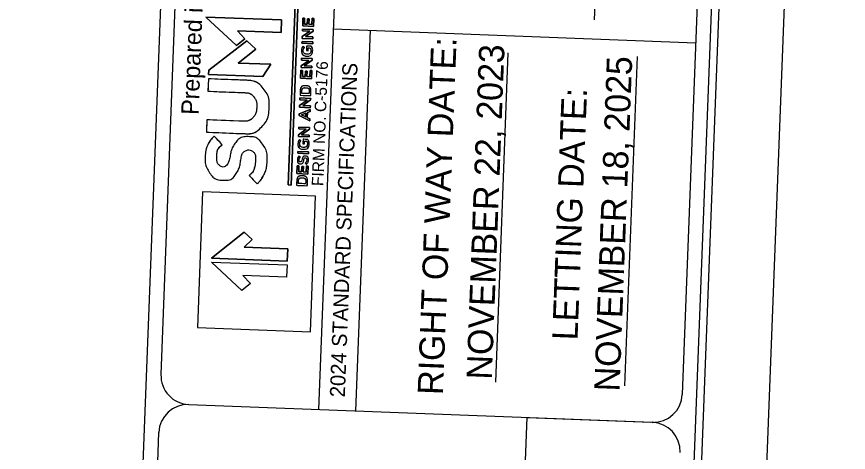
# Model space of a CAD drawing. Extents: x 2094564 to 2100382, y 679033 to 692366.
# Drawn here: x 2098948 to 2100382, y 686841 to 687593 of the extents above; entities that cross this region are included whole.
import ezdxf

# ---------------------------------------------------------------- set-up
doc = ezdxf.new("R2010")
doc.units = 0
for name, color, linetype in [('Old_Level_2', 7, 'Continuous'), ('Prop EOT', 7, 'Continuous'), ('Prop Horizontal Alignment Direction Label', 7, 'Continuous'), ('Prop Horizontal Alignment Tick Label', 7, 'Continuous'), ('Prop Horizontal Alignment Tick Large', 7, 'Continuous'), ('Scratch_Level_0', 7, 'Continuous')]:
    doc.layers.add(name, color=color, linetype=linetype)

msp = doc.modelspace()

# ---------------------------------------------------------------- linework, layer by layer
at = {"layer": 'Old_Level_2'}
for p, q in [((2099444.2, 687539.6), (2099441.8, 687541.8)), ((2099448.4, 687528.2), (2099448.3, 687528.2)), ((2099448.3, 687524.8), (2099448.3, 687524.8)), ((2099446.2, 687470.3), (2099446.2, 687470.3)), ((2099446.3, 687473.7), (2099446.3, 687473.7)), ((2099302.2, 687371.9), (2099288.5, 687386.7)), ((2099438, 687378.7), (2099435.6, 687380.8)), ((2099442.2, 687367.3), (2099442.2, 687367.3)), ((2099436.8, 687350.3), (2099434.4, 687352.2)), ((2099442.1, 687363.9), (2099442.1, 687363.9)), ((2099445.7, 687352.3), (2099445.6, 687352.3)), ((2099436.9, 687342.3), (2099436.8, 687342.3)), ((2099437, 687339), (2099437, 687339)), ((2099445.4, 687339.9), (2099447.7, 687337.8)), ((2099445.8, 687349), (2099445.9, 687349)), ((2099348.7, 687318.8), (2099362.4, 687304.1)), ((2099440.2, 687314.8), (2099440.3, 687314.8)), ((2099440.3, 687318.2), (2099440.3, 687318.2))]:
    msp.add_line(p, q, dxfattribs=at)
for points in [[(2099440.8, 687820.2), (2099420.9, 687302.2), (2099416, 687302.4), (2099435.9, 687820.4), (2099440.8, 687820.2)], [(2099435.9, 687820.4), (2099416, 687302.4), (2099420.9, 687302.2), (2099440.8, 687820.2), (2099435.9, 687820.4)], [(2099274.1, 687592.2), (2099404.4, 687587.2), (2099403.6, 687565.8), (2099328.4, 687568.7), (2099341.4, 687554.9), (2099326.6, 687543), (2099274.1, 687592.2)], [(2099326.6, 687543), (2099341.4, 687554.9), (2099328.4, 687568.7), (2099403.6, 687565.8), (2099404.4, 687587.2), (2099274.1, 687592.2), (2099326.6, 687543)], [(2099441, 687576.9), (2099441.5, 687590.6), (2099444.4, 687590.5), (2099444, 687580), (2099448.8, 687579.8), (2099449.2, 687589.1), (2099452.1, 687589), (2099451.8, 687579.7), (2099456.7, 687579.5), (2099457.2, 687590.2), (2099460.1, 687590), (2099459.5, 687576.2), (2099441, 687576.9)], [(2099459.5, 687576.2), (2099460.1, 687590), (2099457.2, 687590.2), (2099456.7, 687579.5), (2099451.8, 687579.7), (2099452.1, 687589), (2099449.2, 687589.1), (2099448.8, 687579.8), (2099444, 687580), (2099444.4, 687590.5), (2099441.5, 687590.6), (2099441, 687576.9), (2099459.5, 687576.2)], [(2099440.1, 687555.4), (2099440.3, 687558.4), (2099453.5, 687567.9), (2099440.6, 687568.4), (2099440.8, 687571.6), (2099459.3, 687570.9), (2099459.2, 687568.1), (2099445.6, 687558.4), (2099458.8, 687557.9), (2099458.7, 687554.7), (2099440.1, 687555.4)], [(2099458.7, 687554.7), (2099458.8, 687557.9), (2099445.6, 687558.4), (2099459.2, 687568.1), (2099459.3, 687570.9), (2099440.8, 687571.6), (2099440.6, 687568.4), (2099453.5, 687567.9), (2099440.3, 687558.4), (2099440.1, 687555.4), (2099458.7, 687554.7)], [(2099279, 687500.7), (2099344.5, 687551.3), (2099359.9, 687536.7), (2099329.6, 687512.8), (2099386, 687510.7), (2099372.1, 687489.6), (2099278.8, 687493.2), (2099279, 687500.7)], [(2099278.8, 687493.2), (2099372.1, 687489.6), (2099386, 687510.7), (2099329.6, 687512.8), (2099359.9, 687536.7), (2099344.5, 687551.3), (2099279, 687500.7), (2099278.8, 687493.2)], [(2099439.8, 687546.9), (2099439.9, 687550.2), (2099458.5, 687549.5), (2099458.4, 687546.2), (2099439.8, 687546.9)], [(2099458.4, 687546.2), (2099458.5, 687549.5), (2099439.9, 687550.2), (2099439.8, 687546.9), (2099458.4, 687546.2)], [(2099455.6, 687541.9), (2099447.8, 687542.2), (2099447.5, 687534.3), (2099450.4, 687534.2), (2099450.6, 687538.9), (2099454, 687538.8)], [(2099438.2, 687505.1), (2099438.3, 687508.1), (2099451.5, 687517.5), (2099438.7, 687518), (2099438.8, 687521.2), (2099457.4, 687520.5), (2099457.3, 687517.8), (2099443.7, 687508.1), (2099456.9, 687507.6), (2099456.8, 687504.4), (2099438.2, 687505.1)], [(2099456.8, 687504.4), (2099456.9, 687507.6), (2099443.7, 687508.1), (2099457.3, 687517.8), (2099457.4, 687520.5), (2099438.8, 687521.2), (2099438.7, 687518), (2099451.5, 687517.5), (2099438.3, 687508.1), (2099438.2, 687505.1), (2099456.8, 687504.4)], [(2099437.5, 687486.5), (2099438, 687500.3), (2099440.9, 687500.2), (2099440.5, 687489.7), (2099445.4, 687489.5), (2099445.7, 687498.8), (2099448.6, 687498.7), (2099448.3, 687489.4), (2099453.3, 687489.2), (2099453.7, 687499.8), (2099456.6, 687499.7), (2099456.1, 687485.8), (2099437.5, 687486.5)], [(2099456.1, 687485.8), (2099456.6, 687499.7), (2099453.7, 687499.8), (2099453.3, 687489.2), (2099448.3, 687489.4), (2099448.6, 687498.7), (2099445.7, 687498.8), (2099445.4, 687489.5), (2099440.5, 687489.7), (2099440.9, 687500.2), (2099438, 687500.3), (2099437.5, 687486.5), (2099456.1, 687485.8)], [(2099345.7, 687483), (2099278.5, 687485.5), (2099277.6, 687464.2), (2099339.2, 687461.8)], [(2099435.6, 687436.4), (2099435.7, 687439.4), (2099448.9, 687448.9), (2099436.1, 687449.4), (2099436.2, 687452.6), (2099454.8, 687451.9), (2099454.7, 687449.1), (2099441.1, 687439.4), (2099454.3, 687438.9), (2099454.2, 687435.7), (2099435.6, 687436.4)], [(2099454.2, 687435.7), (2099454.3, 687438.9), (2099441.1, 687439.4), (2099454.7, 687449.1), (2099454.8, 687451.9), (2099436.2, 687452.6), (2099436.1, 687449.4), (2099448.9, 687448.9), (2099435.7, 687439.4), (2099435.6, 687436.4), (2099454.2, 687435.7)], [(2099436.6, 687464.2), (2099436.4, 687457.3), (2099455, 687456.6), (2099455.2, 687463.5)], [(2099452.2, 687463.6), (2099452.1, 687460), (2099439.5, 687460.5), (2099439.6, 687464.1)], [(2099434.9, 687422.1), (2099435, 687425.1), (2099454, 687432.5), (2099453.9, 687429.1), (2099449.3, 687427.4), (2099449, 687418.6), (2099453.4, 687416.5), (2099453.3, 687413.2), (2099434.9, 687422.1)], [(2099453.3, 687413.2), (2099453.4, 687416.5), (2099449, 687418.6), (2099449.3, 687427.4), (2099453.9, 687429.1), (2099454, 687432.5), (2099435, 687425.1), (2099434.9, 687422.1), (2099453.3, 687413.2)], [(2099446.4, 687426.3), (2099438.8, 687423.4), (2099446.2, 687419.9), (2099446.4, 687426.3)], [(2099446.2, 687419.9), (2099438.8, 687423.4), (2099446.4, 687426.3), (2099446.2, 687419.9)], [(2099337.3, 687412.5), (2099275.7, 687414.8), (2099274.9, 687393.5), (2099342.2, 687390.9)], [(2099433.6, 687386.1), (2099433.8, 687389.1), (2099447, 687398.5), (2099434.1, 687399), (2099434.3, 687402.2), (2099452.8, 687401.5), (2099452.7, 687398.8), (2099439.1, 687389.1), (2099452.3, 687388.6), (2099452.2, 687385.4), (2099433.6, 687386.1)], [(2099452.2, 687385.4), (2099452.3, 687388.6), (2099439.1, 687389.1), (2099452.7, 687398.8), (2099452.8, 687401.5), (2099434.3, 687402.2), (2099434.1, 687399), (2099447, 687398.5), (2099433.8, 687389.1), (2099433.6, 687386.1), (2099452.2, 687385.4)], [(2099449.5, 687381), (2099441.7, 687381.3), (2099441.4, 687373.4), (2099444.2, 687373.3), (2099444.4, 687378), (2099447.9, 687377.9)], [(2099432.5, 687357.1), (2099432.7, 687360.4), (2099451.2, 687359.6), (2099451.1, 687356.4), (2099432.5, 687357.1)], [(2099451.1, 687356.4), (2099451.2, 687359.6), (2099432.7, 687360.4), (2099432.5, 687357.1), (2099451.1, 687356.4)], [(2099431.2, 687321.9), (2099431.7, 687335.7), (2099434.6, 687335.6), (2099434.2, 687325.1), (2099439.1, 687324.9), (2099439.4, 687334.2), (2099442.3, 687334.1), (2099442, 687324.8), (2099447, 687324.6), (2099447.4, 687335.2), (2099450.3, 687335.1), (2099449.8, 687321.2), (2099431.2, 687321.9)], [(2099449.8, 687321.2), (2099450.3, 687335.1), (2099447.4, 687335.2), (2099447, 687324.6), (2099442, 687324.8), (2099442.3, 687334.1), (2099439.4, 687334.2), (2099439.1, 687324.9), (2099434.2, 687325.1), (2099434.6, 687335.6), (2099431.7, 687335.7), (2099431.2, 687321.9), (2099449.8, 687321.2)], [(2099430.7, 687308.7), (2099430.4, 687301.8), (2099449, 687301.1), (2099449.3, 687308)], [(2099446.3, 687308.1), (2099446.1, 687304.4), (2099433.5, 687304.9), (2099433.6, 687308.6)], [(2099268.3, 687290.3), (2099259.3, 687056.5), (2099454.3, 687049), (2099463.3, 687282.8), (2099268.3, 687290.3)], [(2099268.3, 687290.3), (2099259.3, 687056.5), (2099454.3, 687049), (2099463.3, 687282.8), (2099268.3, 687290.3)], [(2099340, 687221), (2099353.9, 687208), (2099339.9, 687195.3), (2099415.1, 687192.4), (2099414.3, 687171), (2099283.9, 687176), (2099340, 687221)], [(2099283.6, 687169.4), (2099414, 687164.4), (2099413.2, 687143.1), (2099338, 687146), (2099350.9, 687132.2), (2099336.2, 687120.3), (2099283.6, 687169.4)], [(2099283.6, 687169.4), (2099414, 687164.4), (2099413.2, 687143.1), (2099338, 687146), (2099350.9, 687132.2), (2099336.2, 687120.3), (2099283.6, 687169.4)]]:
    msp.add_lwpolyline(points, dxfattribs=at)
msp.add_lwpolyline([(2099283.9, 687176), (2099414.3, 687171), (2099415.1, 687192.4), (2099339.9, 687195.3), (2099353.9, 687208), (2099340, 687221)], close=True, dxfattribs=at)
for points, degree in [([(2099448.3, 687524.8), (2099448.3, 687524.8), (2099448.3, 687524.8), (2099448.3, 687524.8), (2099443.1, 687525), (2099438.8, 687529.2), (2099439, 687534.7), (2099439.2, 687538), (2099440.1, 687539.9), (2099441.8, 687541.8), (2099441.8, 687541.8), (2099444.2, 687539.6), (2099444.2, 687539.6), (2099442.9, 687538.2), (2099442.1, 687536.9), (2099442, 687534.5), (2099441.9, 687531.1), (2099444.8, 687528.4), (2099448.3, 687528.2), (2099448.3, 687528.2), (2099448.4, 687528.2), (2099448.4, 687528.2), (2099452.2, 687528.1), (2099455.1, 687530.5), (2099455.3, 687534.3), (2099455.3, 687536), (2099454.8, 687537.6), (2099454, 687538.8), (2099454, 687538.8), (2099450.6, 687538.9), (2099450.6, 687538.9), (2099450.6, 687538.9), (2099450.4, 687534.2), (2099450.4, 687534.2), (2099450.4, 687534.2), (2099447.5, 687534.3), (2099447.5, 687534.3), (2099447.5, 687534.3), (2099447.8, 687542.2), (2099447.8, 687542.2), (2099447.8, 687542.2), (2099455.6, 687541.9), (2099455.6, 687541.9), (2099457.1, 687540), (2099458.4, 687537.3), (2099458.2, 687534.1), (2099458, 687528.3), (2099453.7, 687524.6), (2099448.3, 687524.8)], 3), ([(2099441.8, 687541.8), (2099440.1, 687539.9), (2099439.2, 687538), (2099439, 687534.7), (2099438.8, 687529.2), (2099443.1, 687525), (2099448.3, 687524.8)], 3), ([(2099448.3, 687528.2), (2099444.8, 687528.4), (2099441.9, 687531.1), (2099442, 687534.5), (2099442.1, 687536.9), (2099442.9, 687538.2), (2099444.2, 687539.6)], 3), ([(2099448.3, 687524.8), (2099453.7, 687524.6), (2099458, 687528.3), (2099458.2, 687534.1), (2099458.4, 687537.3), (2099457.1, 687540), (2099455.6, 687541.9)], 3), ([(2099454, 687538.8), (2099454.8, 687537.6), (2099455.3, 687536), (2099455.3, 687534.3), (2099455.1, 687530.5), (2099452.2, 687528.1), (2099448.4, 687528.2)], 3), ([(2099275.7, 687414.8), (2099275.7, 687414.8), (2099337.3, 687412.5), (2099337.3, 687412.5), (2099345.4, 687412.2), (2099351.4, 687414.4), (2099355.4, 687418.9), (2099359.4, 687423.5), (2099361.5, 687429.4), (2099361.8, 687436.5), (2099362, 687443.6), (2099360.4, 687449.4), (2099356.7, 687454.3), (2099353.1, 687459.2), (2099347.3, 687461.5), (2099339.2, 687461.8), (2099339.2, 687461.8), (2099277.6, 687464.2), (2099277.6, 687464.2), (2099277.6, 687464.2), (2099278.5, 687485.5), (2099278.5, 687485.5), (2099278.5, 687485.5), (2099345.7, 687483), (2099345.7, 687483), (2099356.6, 687482.5), (2099365.7, 687478.1), (2099373, 687469), (2099380.3, 687459.9), (2099383.6, 687448.9), (2099383.1, 687435.6), (2099382.6, 687422.3), (2099378.4, 687411.4), (2099370.5, 687403), (2099362.5, 687394.5), (2099353.1, 687390.5), (2099342.2, 687390.9), (2099342.2, 687390.9), (2099274.9, 687393.5), (2099274.9, 687393.5), (2099274.9, 687393.5), (2099275.7, 687414.8), (2099275.7, 687414.8)], 3), ([(2099342.2, 687390.9), (2099353.1, 687390.5), (2099362.5, 687394.5), (2099370.5, 687403), (2099378.4, 687411.4), (2099382.6, 687422.3), (2099383.1, 687435.6), (2099383.6, 687448.9), (2099380.3, 687459.9), (2099373, 687469), (2099365.7, 687478.1), (2099356.6, 687482.5), (2099345.7, 687483)], 3), ([(2099436.4, 687457.3), (2099436.4, 687457.3), (2099436.6, 687464.2), (2099436.6, 687464.2), (2099436.9, 687470.1), (2099441, 687473.9), (2099446.3, 687473.7), (2099446.3, 687473.7), (2099446.3, 687473.7), (2099446.3, 687473.7), (2099451.5, 687473.5), (2099455.4, 687469.4), (2099455.2, 687463.5), (2099455.2, 687463.5), (2099455, 687456.6), (2099455, 687456.6), (2099455, 687456.6), (2099436.4, 687457.3), (2099436.4, 687457.3)], 3), ([(2099446.3, 687473.7), (2099441, 687473.9), (2099436.9, 687470.1), (2099436.6, 687464.2)], 2), ([(2099439.5, 687460.5), (2099439.5, 687460.5), (2099452.1, 687460), (2099452.1, 687460), (2099452.1, 687460), (2099452.2, 687463.6), (2099452.2, 687463.6), (2099452.4, 687467.5), (2099449.9, 687470.2), (2099446.2, 687470.3), (2099446.2, 687470.3), (2099446.2, 687470.3), (2099446.2, 687470.3), (2099442.5, 687470.5), (2099439.8, 687468), (2099439.6, 687464.1), (2099439.6, 687464.1), (2099439.5, 687460.5), (2099439.5, 687460.5)], 3), ([(2099439.6, 687464.1), (2099439.8, 687468), (2099442.5, 687470.5), (2099446.2, 687470.3)], 2), ([(2099446.2, 687470.3), (2099449.9, 687470.2), (2099452.4, 687467.5), (2099452.2, 687463.6)], 2), ([(2099455.2, 687463.5), (2099455.4, 687469.4), (2099451.5, 687473.5), (2099446.3, 687473.7)], 2), ([(2099339.2, 687461.8), (2099347.3, 687461.5), (2099353.1, 687459.2), (2099356.7, 687454.3), (2099360.4, 687449.4), (2099362, 687443.6), (2099361.8, 687436.5), (2099361.5, 687429.4), (2099359.4, 687423.5), (2099355.4, 687418.9), (2099351.4, 687414.4), (2099345.4, 687412.2), (2099337.3, 687412.5)], 3), ([(2099277.2, 687371.8), (2099279.8, 687377.1), (2099283.6, 687382.1), (2099288.5, 687386.7), (2099288.5, 687386.7), (2099302.2, 687371.9), (2099302.2, 687371.9), (2099296.3, 687367.4), (2099293.2, 687360.8), (2099292.9, 687352.3), (2099292.6, 687343.8), (2099294.4, 687338.2), (2099298.3, 687335.7), (2099302.3, 687333.2), (2099305.7, 687333.1), (2099308.7, 687335.3), (2099311.6, 687337.6), (2099313.9, 687342.9), (2099315.7, 687351.4), (2099317, 687360.4), (2099320.3, 687368.5), (2099325.5, 687375.6), (2099330.8, 687382.8), (2099338.9, 687386.1), (2099349.8, 687385.7), (2099358.4, 687385.4), (2099365.6, 687381.2), (2099371.5, 687373.1), (2099377.3, 687365), (2099380.1, 687355.8), (2099379.7, 687345.3), (2099379.3, 687335.4), (2099377.5, 687327.2), (2099374.4, 687320.7), (2099371.3, 687314.2), (2099367.3, 687308.6), (2099362.4, 687304.1), (2099362.4, 687304.1), (2099348.7, 687318.8), (2099348.7, 687318.8), (2099354.6, 687323.3), (2099358.2, 687331.3), (2099359.6, 687342.6), (2099360, 687352.1), (2099358.2, 687358.1), (2099354.2, 687360.6), (2099350.3, 687363.1), (2099346.2, 687363.3), (2099342.1, 687361.1), (2099338, 687358.9), (2099335.3, 687353.1), (2099333.9, 687343.6), (2099332.7, 687335.1), (2099329.8, 687327.4), (2099325.2, 687320.4), (2099320.7, 687313.5), (2099313.2, 687310.2), (2099302.7, 687310.6), (2099293.3, 687311), (2099285.8, 687315.3), (2099280.4, 687323.6), (2099275, 687331.9), (2099272.5, 687340.3), (2099272.8, 687348.9), (2099273.2, 687358.8), (2099274.6, 687366.4), (2099277.2, 687371.8)], 3), ([(2099288.5, 687386.7), (2099283.6, 687382.1), (2099279.8, 687377.1), (2099277.2, 687371.8)], 2), ([(2099362.4, 687304.1), (2099367.3, 687308.6), (2099371.3, 687314.2), (2099374.4, 687320.7), (2099377.5, 687327.2), (2099379.3, 687335.4), (2099379.7, 687345.3), (2099380.1, 687355.8), (2099377.3, 687365), (2099371.5, 687373.1), (2099365.6, 687381.2), (2099358.4, 687385.4), (2099349.8, 687385.7), (2099338.9, 687386.1), (2099330.8, 687382.8), (2099325.5, 687375.6), (2099320.3, 687368.5), (2099317, 687360.4), (2099315.7, 687351.4), (2099313.9, 687342.9), (2099311.6, 687337.6), (2099308.7, 687335.3), (2099305.7, 687333.1), (2099302.3, 687333.2), (2099298.3, 687335.7), (2099294.4, 687338.2), (2099292.6, 687343.8), (2099292.9, 687352.3), (2099293.2, 687360.8), (2099296.3, 687367.4), (2099302.2, 687371.9)], 3), ([(2099442.1, 687363.9), (2099442.1, 687363.9), (2099442.1, 687363.9), (2099442.1, 687363.9), (2099436.9, 687364.1), (2099432.6, 687368.2), (2099432.9, 687373.8), (2099433, 687377), (2099434, 687379), (2099435.6, 687380.8), (2099435.6, 687380.8), (2099438, 687378.7), (2099438, 687378.7), (2099436.8, 687377.3), (2099435.9, 687375.9), (2099435.8, 687373.6), (2099435.7, 687370.1), (2099438.6, 687367.4), (2099442.2, 687367.3), (2099442.2, 687367.3), (2099442.2, 687367.3), (2099442.2, 687367.3), (2099446, 687367.1), (2099449, 687369.5), (2099449.1, 687373.3), (2099449.2, 687375.1), (2099448.7, 687376.7), (2099447.9, 687377.9), (2099447.9, 687377.9), (2099444.4, 687378), (2099444.4, 687378), (2099444.4, 687378), (2099444.2, 687373.3), (2099444.2, 687373.3), (2099444.2, 687373.3), (2099441.4, 687373.4), (2099441.4, 687373.4), (2099441.4, 687373.4), (2099441.7, 687381.3), (2099441.7, 687381.3), (2099441.7, 687381.3), (2099449.5, 687381), (2099449.5, 687381), (2099451, 687379.1), (2099452.2, 687376.4), (2099452.1, 687373.1), (2099451.8, 687367.3), (2099447.6, 687363.7), (2099442.1, 687363.9)], 3), ([(2099435.6, 687380.8), (2099434, 687379), (2099433, 687377), (2099432.9, 687373.8), (2099432.6, 687368.2), (2099436.9, 687364.1), (2099442.1, 687363.9)], 3), ([(2099442.1, 687363.9), (2099447.6, 687363.7), (2099451.8, 687367.3), (2099452.1, 687373.1), (2099452.2, 687376.4), (2099451, 687379.1), (2099449.5, 687381)], 3), ([(2099277.2, 687371.8), (2099274.6, 687366.4), (2099273.2, 687358.8), (2099272.8, 687348.9), (2099272.5, 687340.3), (2099275, 687331.9), (2099280.4, 687323.6), (2099285.8, 687315.3), (2099293.3, 687311), (2099302.7, 687310.6), (2099313.2, 687310.2), (2099320.7, 687313.5), (2099325.2, 687320.4), (2099329.8, 687327.4), (2099332.7, 687335.1), (2099333.9, 687343.6), (2099335.3, 687353.1), (2099338, 687358.9), (2099342.1, 687361.1), (2099346.2, 687363.3), (2099350.3, 687363.1), (2099354.2, 687360.6), (2099358.2, 687358.1), (2099360, 687352.1), (2099359.6, 687342.6), (2099358.2, 687331.3), (2099354.6, 687323.3), (2099348.7, 687318.8)], 3), ([(2099442.2, 687367.3), (2099438.6, 687367.4), (2099435.7, 687370.1), (2099435.8, 687373.6), (2099435.9, 687375.9), (2099436.8, 687377.3), (2099438, 687378.7)], 3), ([(2099447.9, 687377.9), (2099448.7, 687376.7), (2099449.2, 687375.1), (2099449.1, 687373.3), (2099449, 687369.5), (2099446, 687367.1), (2099442.2, 687367.3)], 3), ([(2099447.7, 687337.8), (2099447.7, 687337.8), (2099445.4, 687339.9), (2099445.4, 687339.9), (2099447, 687341.6), (2099448, 687343.4), (2099448.1, 687345.7), (2099448.1, 687347.7), (2099447.2, 687349), (2099445.9, 687349), (2099445.9, 687349), (2099445.8, 687349), (2099445.8, 687349), (2099444.5, 687349.1), (2099443.7, 687348.4), (2099442.8, 687345), (2099441.7, 687341), (2099440.4, 687338.9), (2099437, 687339), (2099437, 687339), (2099437, 687339), (2099437, 687339), (2099433.8, 687339.1), (2099431.7, 687341.9), (2099431.8, 687345.5), (2099431.9, 687348.2), (2099432.8, 687350.3), (2099434.4, 687352.2), (2099434.4, 687352.2), (2099436.8, 687350.3), (2099436.8, 687350.3), (2099435.5, 687348.7), (2099434.8, 687347.1), (2099434.7, 687345.4), (2099434.6, 687343.5), (2099435.6, 687342.3), (2099436.8, 687342.3), (2099436.8, 687342.3), (2099436.9, 687342.3), (2099436.9, 687342.3), (2099438.3, 687342.2), (2099439, 687343), (2099439.9, 687346.6), (2099441, 687350.5), (2099442.5, 687352.4), (2099445.6, 687352.3), (2099445.6, 687352.3), (2099445.7, 687352.3), (2099445.7, 687352.3), (2099449.1, 687352.2), (2099451.1, 687349.4), (2099451, 687345.5), (2099450.8, 687342.6), (2099449.8, 687340), (2099447.7, 687337.8)], 3), ([(2099434.4, 687352.2), (2099432.8, 687350.3), (2099431.9, 687348.2), (2099431.8, 687345.5), (2099431.7, 687341.9), (2099433.8, 687339.1), (2099437, 687339)], 3), ([(2099436.8, 687342.3), (2099435.6, 687342.3), (2099434.6, 687343.5), (2099434.7, 687345.4), (2099434.8, 687347.1), (2099435.5, 687348.7), (2099436.8, 687350.3)], 3), ([(2099445.6, 687352.3), (2099442.5, 687352.4), (2099441, 687350.5), (2099439.9, 687346.6), (2099439, 687343), (2099438.3, 687342.2), (2099436.9, 687342.3)], 3), ([(2099447.7, 687337.8), (2099449.8, 687340), (2099450.8, 687342.6), (2099451, 687345.5), (2099451.1, 687349.4), (2099449.1, 687352.2), (2099445.7, 687352.3)], 3), ([(2099437, 687339), (2099440.4, 687338.9), (2099441.7, 687341), (2099442.8, 687345), (2099443.7, 687348.4), (2099444.5, 687349.1), (2099445.8, 687349)], 3), ([(2099445.9, 687349), (2099447.2, 687349), (2099448.1, 687347.7), (2099448.1, 687345.7), (2099448, 687343.4), (2099447, 687341.6), (2099445.4, 687339.9)], 3), ([(2099430.4, 687301.8), (2099430.4, 687301.8), (2099430.7, 687308.7), (2099430.7, 687308.7), (2099430.9, 687314.5), (2099435.1, 687318.4), (2099440.3, 687318.2), (2099440.3, 687318.2), (2099440.3, 687318.2), (2099440.3, 687318.2), (2099445.6, 687318), (2099449.5, 687313.8), (2099449.3, 687308), (2099449.3, 687308), (2099449, 687301.1), (2099449, 687301.1), (2099449, 687301.1), (2099430.4, 687301.8), (2099430.4, 687301.8)], 3), ([(2099440.3, 687318.2), (2099435.1, 687318.4), (2099430.9, 687314.5), (2099430.7, 687308.7)], 2), ([(2099433.5, 687304.9), (2099433.5, 687304.9), (2099446.1, 687304.4), (2099446.1, 687304.4), (2099446.1, 687304.4), (2099446.3, 687308.1), (2099446.3, 687308.1), (2099446.4, 687312), (2099443.9, 687314.6), (2099440.3, 687314.8), (2099440.3, 687314.8), (2099440.2, 687314.8), (2099440.2, 687314.8), (2099436.6, 687314.9), (2099433.8, 687312.5), (2099433.6, 687308.6), (2099433.6, 687308.6), (2099433.5, 687304.9), (2099433.5, 687304.9)], 3), ([(2099433.6, 687308.6), (2099433.8, 687312.5), (2099436.6, 687314.9), (2099440.2, 687314.8)], 2), ([(2099449.3, 687308), (2099449.5, 687313.8), (2099445.6, 687318), (2099440.3, 687318.2)], 2), ([(2099440.3, 687314.8), (2099443.9, 687314.6), (2099446.4, 687312), (2099446.3, 687308.1)], 2)]:
    msp.add_open_spline(points, degree=degree, dxfattribs=at)
at = {"layer": 'Prop EOT'}
msp.add_lwpolyline([(2099967.1, 684894.2), (2099751.5, 684902.4), (2099828.1, 686901.2), (2100041.6, 686892.9)], dxfattribs=at)
at = {"layer": 'Prop Horizontal Alignment Direction Label'}
for p, q in [((2099030, 683278.9), (2099302.1, 690373.6)), ((2099526.9, 688438.6), (2099468.4, 686914.7)), ((2099196.8, 686975.2), (2099251.4, 688399.1)), ((2099944.5, 687587.5), (2099974.5, 688368.2)), ((2099493.6, 687572), (2100119.4, 687548)), ((2099557.4, 687569.6), (2099532.1, 686912.3)), ((2099795.2, 687530.4), (2099773.5, 686962.1)), ((2100018.2, 687523.9), (2099996.4, 686955.5)), ((2099550.1, 687380.2), (2099550.1, 687380.2)), ((2099784.4, 687246.1), (2099784.4, 687246.1)), ((2099244.8, 686923.3), (2100044.2, 686892.7)), ((2099120.2, 684976.7), (2099193, 686875.3))]:
    msp.add_line(p, q, dxfattribs=at)
for points in [[(2099968.8, 682967.7), (2100252.4, 690362.2)], [(2100096.1, 686940.7), (2100150.8, 688364.6)]]:
    msp.add_lwpolyline(points, dxfattribs=at)
for centre, start, end in [((2099246.5, 686973.3), 177.8037, 267.8037), ((2100045.9, 686942.6), 267.8037, 357.8037), ((2099242.7, 686873.4), 87.8037, 177.8037), ((2100042.1, 686842.7), 357.8037, 87.8037)]:
    msp.add_arc(centre, 50, start, end, dxfattribs=at)
at = {"layer": 'Prop Horizontal Alignment Tick Label'}
msp.add_lwpolyline([(2099950.1, 682147.8), (2100269.5, 690474.2), (2094997.8, 690676.3), (2094678.5, 682349.9)], close=True, dxfattribs=at)
at = {"layer": 'Prop Horizontal Alignment Tick Large'}
msp.add_lwpolyline([(2094886.5, 690703.1), (2094563.9, 682289.3), (2100059.8, 682078.5), (2100382.4, 690492.3)], close=True, dxfattribs=at)

# ---------------------------------------------------------------- texts
at = {"layer": 'Old_Level_2'}
msp.add_text('FIRM NO. C-5176', height=20.01, rotation=87.8037, dxfattribs=at).set_placement((2099476.5, 687300.2))
at = {"layer": 'Prop Horizontal Alignment Direction Label'}
for s, height, p in [('Prepared in the Office of:', 29.997, (2099261.3, 687423)), ('RIGHT OF WAY DATE: ', 43.749, (2099683, 686939.3)), ('2024 STANDARD SPECIFICATIONS', 26, (2099513.7, 686935.5)), ('LETTING DATE:', 43.749, (2099915.1, 687033.7))]:
    msp.add_text(s, height=height, rotation=87.8037, dxfattribs=at).set_placement(p)
at = {"layer": 'Scratch_Level_0'}
for s, p in [('NOVEMBER 22, 2023', (2099767.2, 686965.9)), ('NOVEMBER 18, 2025', (2099987.5, 686945.4))]:
    msp.add_text(s, height=43.75, rotation=87.8037, dxfattribs=at).set_placement(p)

doc.saveas('drawing.dxf')
